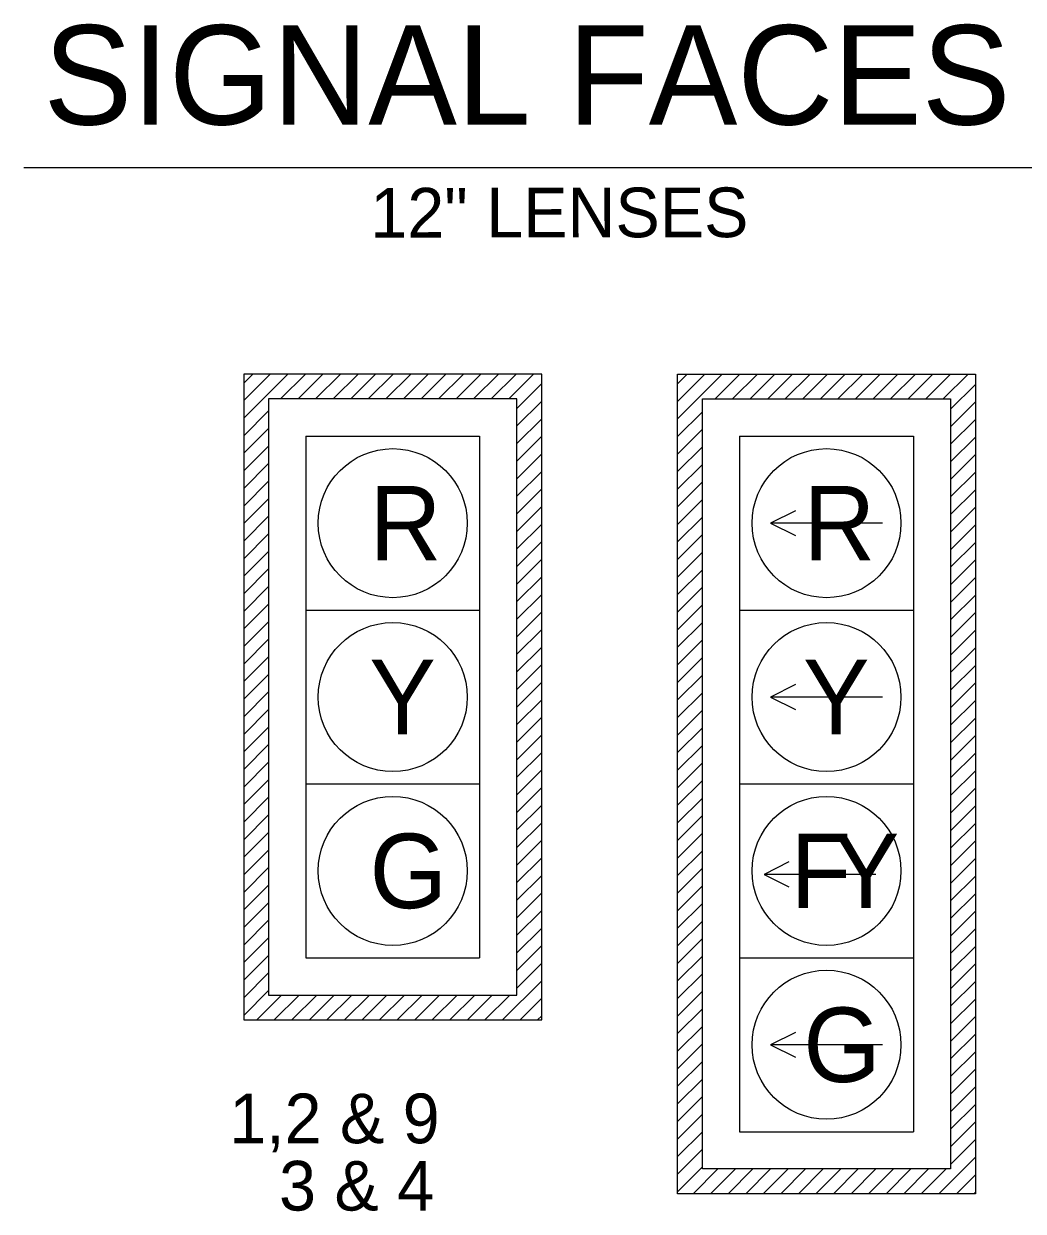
# Model space of a CAD drawing. Extents: x 1280742 to 1281742, y 1892348 to 1892988.
# Drawn here: x 1280924.2 to 1281004.7, y 1892484.2 to 1892579.8 of the extents above; entities that cross this region are included whole.
import ezdxf

# ---------------------------------------------------------------- set-up
doc = ezdxf.new("R2010")
doc.units = 0
doc.layers.add('T_Drafting', color=7, linetype='Continuous')
doc.layers.add('T_Notes', color=7, linetype='Continuous')

msp = doc.modelspace()

# ---------------------------------------------------------------- linework, layer by layer
at = {"layer": 'T_Drafting'}
for p, q in [((1280965.948, 1892551.61), (1280941.948, 1892551.61)), ((1280941.948, 1892551.61), (1280941.948, 1892499.61)), ((1280941.948, 1892548.063), (1280945.495, 1892551.61)), ((1280941.948, 1892549.477), (1280944.081, 1892551.61)), ((1280941.948, 1892550.891), (1280942.666, 1892551.61)), ((1280944.909, 1892549.61), (1280946.909, 1892551.61)), ((1280946.323, 1892549.61), (1280948.323, 1892551.61)), ((1280947.738, 1892549.61), (1280949.738, 1892551.61)), ((1280949.152, 1892549.61), (1280951.152, 1892551.61)), ((1280950.566, 1892549.61), (1280952.566, 1892551.61)), ((1280951.98, 1892549.61), (1280953.98, 1892551.61)), ((1280953.394, 1892549.61), (1280955.394, 1892551.61)), ((1280954.809, 1892549.61), (1280956.809, 1892551.61)), ((1280956.223, 1892549.61), (1280958.223, 1892551.61)), ((1280957.637, 1892549.61), (1280959.637, 1892551.61)), ((1280959.051, 1892549.61), (1280961.051, 1892551.61)), ((1280960.465, 1892549.61), (1280962.465, 1892551.61)), ((1280961.88, 1892549.61), (1280963.88, 1892551.61)), ((1280963.294, 1892549.61), (1280965.294, 1892551.61)), ((1280965.948, 1892499.61), (1280965.948, 1892551.61)), ((1280976.886, 1892485.61), (1280976.886, 1892551.61)), ((1280976.886, 1892551.61), (1281000.886, 1892551.61)), ((1280976.886, 1892548.003), (1280980.493, 1892551.61)), ((1280976.886, 1892549.417), (1280979.079, 1892551.61)), ((1280976.886, 1892550.831), (1280977.665, 1892551.61)), ((1280979.907, 1892549.61), (1280981.907, 1892551.61)), ((1280981.321, 1892549.61), (1280983.321, 1892551.61)), ((1280982.736, 1892549.61), (1280984.736, 1892551.61)), ((1280984.15, 1892549.61), (1280986.15, 1892551.61)), ((1280985.564, 1892549.61), (1280987.564, 1892551.61)), ((1280986.978, 1892549.61), (1280988.978, 1892551.61)), ((1280988.393, 1892549.61), (1280990.393, 1892551.61)), ((1280989.807, 1892549.61), (1280991.807, 1892551.61)), ((1280991.221, 1892549.61), (1280993.221, 1892551.61)), ((1280992.635, 1892549.61), (1280994.635, 1892551.61)), ((1280994.049, 1892549.61), (1280996.049, 1892551.61)), ((1280995.464, 1892549.61), (1280997.464, 1892551.61)), ((1280996.878, 1892549.61), (1280998.878, 1892551.61)), ((1280998.292, 1892549.61), (1281000.292, 1892551.61)), ((1281000.886, 1892551.61), (1281000.886, 1892485.61)), ((1280963.948, 1892548.85), (1280965.948, 1892550.85)), ((1280998.886, 1892548.789), (1281000.886, 1892550.789)), ((1280963.948, 1892547.436), (1280965.948, 1892549.436)), ((1280998.886, 1892547.375), (1281000.886, 1892549.375)), ((1280941.948, 1892546.649), (1280943.948, 1892548.649)), ((1280963.948, 1892546.021), (1280965.948, 1892548.021)), ((1280976.886, 1892546.588), (1280978.886, 1892548.588)), ((1280998.886, 1892545.961), (1281000.886, 1892547.961)), ((1280941.948, 1892545.235), (1280943.948, 1892547.235)), ((1280976.886, 1892545.174), (1280978.886, 1892547.174)), ((1280946.948, 1892546.61), (1280960.948, 1892546.61)), ((1280946.948, 1892546.61), (1280946.948, 1892532.61)), ((1280960.948, 1892546.61), (1280960.948, 1892532.61)), ((1280963.948, 1892544.607), (1280965.948, 1892546.607)), ((1280981.886, 1892546.61), (1280995.886, 1892546.61)), ((1280981.886, 1892546.61), (1280981.886, 1892532.61)), ((1280995.886, 1892546.61), (1280995.886, 1892532.61)), ((1280998.886, 1892544.547), (1281000.886, 1892546.547)), ((1280941.948, 1892543.82), (1280943.948, 1892545.82)), ((1280963.948, 1892543.193), (1280965.948, 1892545.193)), ((1280976.886, 1892543.76), (1280978.886, 1892545.76)), ((1280998.886, 1892543.133), (1281000.886, 1892545.133)), ((1280941.948, 1892542.406), (1280943.948, 1892544.406)), ((1280976.886, 1892542.346), (1280978.886, 1892544.346)), ((1280941.948, 1892540.992), (1280943.948, 1892542.992)), ((1280963.948, 1892541.779), (1280965.948, 1892543.779)), ((1280998.886, 1892541.718), (1281000.886, 1892543.718)), ((1280963.948, 1892540.364), (1280965.948, 1892542.364)), ((1280976.886, 1892540.932), (1280978.886, 1892542.932)), ((1280998.886, 1892540.304), (1281000.886, 1892542.304)), ((1280941.948, 1892539.578), (1280943.948, 1892541.578)), ((1280976.886, 1892539.517), (1280978.886, 1892541.517)), ((1280941.948, 1892538.163), (1280943.948, 1892540.163)), ((1280963.948, 1892538.95), (1280965.948, 1892540.95)), ((1280998.886, 1892538.89), (1281000.886, 1892540.89)), ((1280963.948, 1892537.536), (1280965.948, 1892539.536)), ((1280976.886, 1892538.103), (1280978.886, 1892540.103)), ((1280993.386, 1892539.61), (1280984.386, 1892539.61)), ((1280998.886, 1892537.476), (1281000.886, 1892539.476)), ((1280941.948, 1892536.749), (1280943.948, 1892538.749)), ((1280976.886, 1892536.689), (1280978.886, 1892538.689)), ((1280941.948, 1892535.335), (1280943.948, 1892537.335)), ((1280963.948, 1892536.122), (1280965.948, 1892538.122)), ((1280976.886, 1892535.275), (1280978.886, 1892537.275)), ((1280998.886, 1892536.062), (1281000.886, 1892538.062)), ((1280963.948, 1892534.708), (1280965.948, 1892536.708)), ((1280998.886, 1892534.647), (1281000.886, 1892536.647)), ((1280941.948, 1892533.921), (1280943.948, 1892535.921)), ((1280976.886, 1892533.861), (1280978.886, 1892535.861)), ((1280941.948, 1892532.507), (1280943.948, 1892534.507)), ((1280963.948, 1892533.293), (1280965.948, 1892535.293)), ((1280976.886, 1892532.446), (1280978.886, 1892534.446)), ((1280998.886, 1892533.233), (1281000.886, 1892535.233)), ((1280963.948, 1892531.879), (1280965.948, 1892533.879)), ((1280998.886, 1892531.819), (1281000.886, 1892533.819)), ((1280941.948, 1892531.092), (1280943.948, 1892533.092)), ((1280946.948, 1892532.61), (1280960.948, 1892532.61)), ((1280946.948, 1892532.61), (1280946.948, 1892518.61)), ((1280960.948, 1892532.61), (1280960.948, 1892518.61)), ((1280963.948, 1892530.465), (1280965.948, 1892532.465)), ((1280976.886, 1892531.032), (1280978.886, 1892533.032)), ((1280981.886, 1892532.61), (1280995.886, 1892532.61)), ((1280981.886, 1892532.61), (1280981.886, 1892518.61)), ((1280995.886, 1892532.61), (1280995.886, 1892518.61)), ((1280941.948, 1892529.678), (1280943.948, 1892531.678)), ((1280976.886, 1892529.618), (1280978.886, 1892531.618)), ((1280998.886, 1892530.405), (1281000.886, 1892532.405)), ((1280963.948, 1892529.051), (1280965.948, 1892531.051)), ((1280998.886, 1892528.99), (1281000.886, 1892530.99)), ((1280941.948, 1892528.264), (1280943.948, 1892530.264)), ((1280963.948, 1892527.637), (1280965.948, 1892529.637)), ((1280976.886, 1892528.204), (1280978.886, 1892530.204)), ((1280941.948, 1892526.85), (1280943.948, 1892528.85)), ((1280976.886, 1892526.789), (1280978.886, 1892528.789)), ((1280998.886, 1892527.576), (1281000.886, 1892529.576)), ((1280963.948, 1892526.222), (1280965.948, 1892528.222)), ((1280998.886, 1892526.162), (1281000.886, 1892528.162)), ((1280941.948, 1892525.436), (1280943.948, 1892527.436)), ((1280963.948, 1892524.808), (1280965.948, 1892526.808)), ((1280976.886, 1892525.375), (1280978.886, 1892527.375)), ((1280998.886, 1892524.748), (1281000.886, 1892526.748)), ((1280941.948, 1892524.021), (1280943.948, 1892526.021)), ((1280976.886, 1892523.961), (1280978.886, 1892525.961)), ((1280963.948, 1892523.394), (1280965.948, 1892525.394)), ((1280993.386, 1892525.61), (1280984.386, 1892525.61)), ((1280998.886, 1892523.334), (1281000.886, 1892525.334)), ((1280941.948, 1892522.607), (1280943.948, 1892524.607)), ((1280963.948, 1892521.98), (1280965.948, 1892523.98)), ((1280976.886, 1892522.547), (1280978.886, 1892524.547)), ((1280998.886, 1892521.919), (1281000.886, 1892523.919)), ((1280941.948, 1892521.193), (1280943.948, 1892523.193)), ((1280976.886, 1892521.133), (1280978.886, 1892523.133)), ((1280963.948, 1892520.565), (1280965.948, 1892522.565)), ((1280998.886, 1892520.505), (1281000.886, 1892522.505)), ((1280941.948, 1892519.779), (1280943.948, 1892521.779)), ((1280963.948, 1892519.151), (1280965.948, 1892521.151)), ((1280976.886, 1892519.718), (1280978.886, 1892521.718)), ((1280998.886, 1892519.091), (1281000.886, 1892521.091)), ((1280941.948, 1892518.364), (1280943.948, 1892520.364)), ((1280976.886, 1892518.304), (1280978.886, 1892520.304)), ((1280963.948, 1892517.737), (1280965.948, 1892519.737)), ((1280998.886, 1892517.677), (1281000.886, 1892519.677)), ((1280941.948, 1892516.95), (1280943.948, 1892518.95)), ((1280946.948, 1892518.61), (1280960.948, 1892518.61)), ((1280946.948, 1892518.61), (1280946.948, 1892504.61)), ((1280960.948, 1892518.61), (1280960.948, 1892504.61)), ((1280963.948, 1892516.323), (1280965.948, 1892518.323)), ((1280976.886, 1892516.89), (1280978.886, 1892518.89)), ((1280981.886, 1892518.61), (1280995.886, 1892518.61)), ((1280981.886, 1892518.61), (1280981.886, 1892504.61)), ((1280995.886, 1892518.61), (1280995.886, 1892504.61)), ((1280998.886, 1892516.263), (1281000.886, 1892518.263)), ((1280941.948, 1892515.536), (1280943.948, 1892517.536)), ((1280976.886, 1892515.476), (1280978.886, 1892517.476)), ((1280963.948, 1892514.909), (1280965.948, 1892516.909)), ((1280998.886, 1892514.848), (1281000.886, 1892516.848)), ((1280941.948, 1892514.122), (1280943.948, 1892516.122)), ((1280963.948, 1892513.494), (1280965.948, 1892515.494)), ((1280976.886, 1892514.062), (1280978.886, 1892516.062)), ((1280998.886, 1892513.434), (1281000.886, 1892515.434)), ((1280941.948, 1892512.708), (1280943.948, 1892514.708)), ((1280976.886, 1892512.647), (1280978.886, 1892514.647)), ((1280963.948, 1892512.08), (1280965.948, 1892514.08)), ((1280998.886, 1892512.02), (1281000.886, 1892514.02)), ((1280941.948, 1892511.293), (1280943.948, 1892513.293)), ((1280963.948, 1892510.666), (1280965.948, 1892512.666)), ((1280976.886, 1892511.233), (1280978.886, 1892513.233)), ((1280998.886, 1892510.606), (1281000.886, 1892512.606)), ((1280941.948, 1892509.879), (1280943.948, 1892511.879)), ((1280976.886, 1892509.819), (1280978.886, 1892511.819)), ((1280963.948, 1892509.252), (1280965.948, 1892511.252)), ((1280992.861, 1892511.332), (1280983.861, 1892511.332)), ((1280998.886, 1892509.191), (1281000.886, 1892511.191)), ((1280941.948, 1892508.465), (1280943.948, 1892510.465)), ((1280963.948, 1892507.838), (1280965.948, 1892509.838)), ((1280976.886, 1892508.405), (1280978.886, 1892510.405)), ((1280998.886, 1892507.777), (1281000.886, 1892509.777)), ((1280941.948, 1892507.051), (1280943.948, 1892509.051)), ((1280976.886, 1892506.99), (1280978.886, 1892508.99)), ((1280941.948, 1892505.637), (1280943.948, 1892507.637)), ((1280963.948, 1892506.423), (1280965.948, 1892508.423)), ((1280998.886, 1892506.363), (1281000.886, 1892508.363)), ((1280963.948, 1892505.009), (1280965.948, 1892507.009)), ((1280976.886, 1892505.576), (1280978.886, 1892507.576)), ((1280998.886, 1892504.949), (1281000.886, 1892506.949)), ((1280941.948, 1892504.222), (1280943.948, 1892506.222)), ((1280976.886, 1892504.162), (1280978.886, 1892506.162)), ((1280941.948, 1892502.808), (1280943.948, 1892504.808)), ((1280963.948, 1892503.595), (1280965.948, 1892505.595)), ((1280976.886, 1892502.748), (1280978.886, 1892504.748)), ((1280998.886, 1892503.535), (1281000.886, 1892505.535)), ((1280946.948, 1892504.61), (1280960.948, 1892504.61)), ((1280963.948, 1892502.181), (1280965.948, 1892504.181)), ((1280981.886, 1892504.61), (1280995.886, 1892504.61)), ((1280981.886, 1892504.61), (1280981.886, 1892490.61)), ((1280995.886, 1892504.61), (1280995.886, 1892490.61)), ((1280998.886, 1892502.12), (1281000.886, 1892504.12)), ((1280941.948, 1892501.394), (1280943.948, 1892503.394)), ((1280976.886, 1892501.334), (1280978.886, 1892503.334)), ((1280941.948, 1892499.98), (1280943.948, 1892501.98)), ((1280962.791, 1892499.61), (1280965.948, 1892502.766)), ((1280976.886, 1892499.919), (1280978.886, 1892501.919)), ((1280998.886, 1892500.706), (1281000.886, 1892502.706)), ((1280942.992, 1892499.61), (1280944.992, 1892501.61)), ((1280944.407, 1892499.61), (1280946.407, 1892501.61)), ((1280945.821, 1892499.61), (1280947.821, 1892501.61)), ((1280947.235, 1892499.61), (1280949.235, 1892501.61)), ((1280948.649, 1892499.61), (1280950.649, 1892501.61)), ((1280950.063, 1892499.61), (1280952.063, 1892501.61)), ((1280951.478, 1892499.61), (1280953.478, 1892501.61)), ((1280952.892, 1892499.61), (1280954.892, 1892501.61)), ((1280954.306, 1892499.61), (1280956.306, 1892501.61)), ((1280955.72, 1892499.61), (1280957.72, 1892501.61)), ((1280957.134, 1892499.61), (1280959.134, 1892501.61)), ((1280958.549, 1892499.61), (1280960.549, 1892501.61)), ((1280959.963, 1892499.61), (1280961.963, 1892501.61)), ((1280961.377, 1892499.61), (1280963.377, 1892501.61)), ((1280964.206, 1892499.61), (1280965.948, 1892501.352)), ((1280998.886, 1892499.292), (1281000.886, 1892501.292)), ((1280976.886, 1892498.505), (1280978.886, 1892500.505)), ((1280941.948, 1892499.61), (1280965.948, 1892499.61)), ((1280965.62, 1892499.61), (1280965.948, 1892499.938)), ((1280976.886, 1892497.091), (1280978.886, 1892499.091)), ((1280998.886, 1892497.878), (1281000.886, 1892499.878)), ((1280998.886, 1892496.464), (1281000.886, 1892498.464)), ((1280976.886, 1892495.677), (1280978.886, 1892497.677)), ((1280993.386, 1892497.61), (1280984.386, 1892497.61)), ((1280976.886, 1892494.263), (1280978.886, 1892496.263)), ((1280998.886, 1892495.049), (1281000.886, 1892497.049)), ((1280998.886, 1892493.635), (1281000.886, 1892495.635)), ((1280976.886, 1892492.848), (1280978.886, 1892494.848)), ((1280998.886, 1892492.221), (1281000.886, 1892494.221)), ((1280976.886, 1892491.434), (1280978.886, 1892493.434)), ((1280998.886, 1892490.807), (1281000.886, 1892492.807)), ((1280976.886, 1892490.02), (1280978.886, 1892492.02)), ((1280998.886, 1892489.392), (1281000.886, 1892491.392)), ((1280976.886, 1892488.606), (1280978.886, 1892490.606)), ((1280981.886, 1892490.61), (1280995.886, 1892490.61)), ((1280998.886, 1892487.978), (1281000.886, 1892489.978)), ((1280976.886, 1892487.191), (1280978.886, 1892489.191)), ((1280997.932, 1892485.61), (1281000.886, 1892488.564)), ((1280976.886, 1892485.777), (1280978.886, 1892487.777)), ((1280978.133, 1892485.61), (1280980.133, 1892487.61)), ((1280979.547, 1892485.61), (1280981.547, 1892487.61)), ((1280980.961, 1892485.61), (1280982.961, 1892487.61)), ((1280982.375, 1892485.61), (1280984.375, 1892487.61)), ((1280983.79, 1892485.61), (1280985.79, 1892487.61)), ((1280985.204, 1892485.61), (1280987.204, 1892487.61)), ((1280986.618, 1892485.61), (1280988.618, 1892487.61)), ((1280988.032, 1892485.61), (1280990.032, 1892487.61)), ((1280989.446, 1892485.61), (1280991.446, 1892487.61)), ((1280990.861, 1892485.61), (1280992.861, 1892487.61)), ((1280992.275, 1892485.61), (1280994.275, 1892487.61)), ((1280993.689, 1892485.61), (1280995.689, 1892487.61)), ((1280995.103, 1892485.61), (1280997.103, 1892487.61)), ((1280996.517, 1892485.61), (1280998.517, 1892487.61)), ((1280999.346, 1892485.61), (1281000.886, 1892487.15)), ((1281000.886, 1892485.61), (1280976.886, 1892485.61)), ((1281000.76, 1892485.61), (1281000.886, 1892485.736))]:
    msp.add_line(p, q, dxfattribs=at)
for points in [[(1280963.948, 1892501.61), (1280963.948, 1892549.61), (1280943.948, 1892549.61), (1280943.948, 1892501.61)], [(1280978.886, 1892487.61), (1280978.886, 1892549.61), (1280998.886, 1892549.61), (1280998.886, 1892487.61)]]:
    msp.add_lwpolyline(points, close=True, dxfattribs=at)
for points in [[(1280986.386, 1892540.61), (1280984.386, 1892539.61), (1280986.386, 1892538.61)], [(1280986.386, 1892526.61), (1280984.386, 1892525.61), (1280986.386, 1892524.61)], [(1280985.861, 1892512.332), (1280983.861, 1892511.332), (1280985.861, 1892510.332)], [(1280986.386, 1892498.61), (1280984.386, 1892497.61), (1280986.386, 1892496.61)]]:
    msp.add_lwpolyline(points, dxfattribs=at)
for centre in [(1280953.948, 1892539.61), (1280988.886, 1892539.61), (1280953.948, 1892525.61), (1280988.886, 1892525.61), (1280953.948, 1892511.61), (1280988.886, 1892511.61), (1280988.886, 1892497.61)]:
    msp.add_circle(centre, 6, dxfattribs=at)
at = {"layer": 'T_Notes'}
msp.add_line((1280924.224, 1892568.237), (1281022.409, 1892568.237), dxfattribs=at)

# ---------------------------------------------------------------- texts
at = {"layer": 'T_Drafting'}
msp.add_text('12" LENSES', height=4, rotation=0.07203, dxfattribs=at).set_placement((1280952.15, 1892562.603))
for s, p in [('R', (1280952.083, 1892536.611)), ('R', (1280987.021, 1892536.611)), ('Y', (1280952.059, 1892522.611)), ('Y', (1280986.997, 1892522.611)), ('G', (1280952.082, 1892508.611)), ('F', (1280985.981, 1892508.611)), ('Y', (1280989.406, 1892508.611)), ('G', (1280987.02, 1892494.611))]:
    msp.add_text(s, height=5.998, dxfattribs=at).set_placement(p)
at = {"layer": 'T_Notes'}
for s, height, p in [('SIGNAL FACES', 8, (1280925.823, 1892571.706)), ('1,2 & 9', 4, (1280940.773, 1892489.679)), ('3 & 4', 4, (1280944.792, 1892484.261))]:
    msp.add_text(s, height=height, dxfattribs=at).set_placement(p)

doc.saveas('drawing.dxf')
